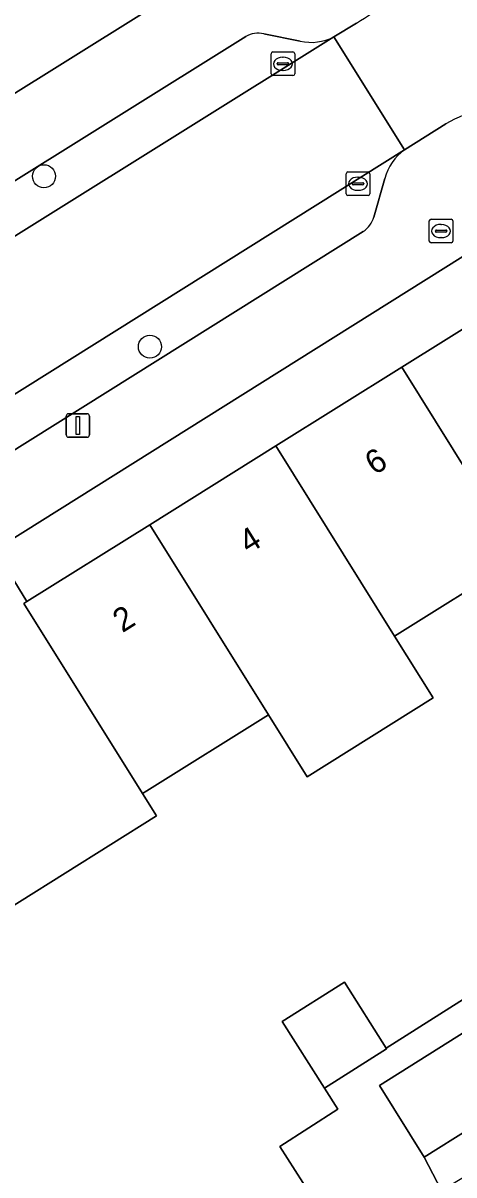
# Model space of a CAD drawing. Extents: x 159664 to 160323, y 385312 to 386115.
# Drawn here: x 160024.46 to 160042.74, y 385782.67 to 385831.48 of the extents above; entities that cross this region are included whole.
import ezdxf

# ---------------------------------------------------------------- set-up
doc = ezdxf.new("R2010")
doc.units = 0
for name, color, linetype in [('IMGEO_Boom', 7, 'Continuous'), ('IMGEO_Brandkraan', 7, 'Continuous'), ('IMGEO_Erf', 7, 'Continuous'), ('IMGEO_Kolk', 7, 'Continuous'), ('IMGEO_Lichtmast', 7, 'Continuous'), ('IMGEO_Pand', 7, 'Continuous'), ('IMGEO_Pand_nummerreeks', 7, 'Continuous'), ('IMGEO_Parkeervlak_open', 7, 'Continuous'), ('IMGEO_Rijbaan_lokaal_open', 7, 'Continuous'), ('IMGEO_Voetpad_open', 7, 'Continuous')]:
    doc.layers.add(name, color=color, linetype=linetype)

msp = doc.modelspace()

# ---------------------------------------------------------------- linework, layer by layer
at = {"layer": 'IMGEO_Boom'}
for centre in [(160025.351, 385824.986), (160029.844, 385817.765)]:
    msp.add_circle(centre, 0.489, dxfattribs=at)
at = {"layer": 'IMGEO_Brandkraan'}
for p, q in [((160041.691, 385822.238), (160041.691, 385823.09)), ((160041.766, 385823.164), (160042.618, 385823.164)), ((160042.179, 385822.944), (160042.204, 385822.944)), ((160042.692, 385823.09), (160042.692, 385822.238)), ((160041.95, 385822.658), (160041.95, 385822.67)), ((160042.388, 385822.621), (160041.99, 385822.621)), ((160041.993, 385822.707), (160042.391, 385822.707)), ((160042.434, 385822.67), (160042.434, 385822.658)), ((160042.618, 385822.164), (160041.766, 385822.164)), ((160042.202, 385822.384), (160042.177, 385822.384))]:
    msp.add_line(p, q, dxfattribs=at)
for points in [[(160041.691, 385822.238), (160041.691, 385823.09)], [(160041.766, 385823.164), (160042.618, 385823.164)], [(160042.692, 385823.09), (160042.692, 385822.238)], [(160042.618, 385822.164), (160041.766, 385822.164)]]:
    msp.add_lwpolyline(points, dxfattribs=at)
for centre, radius, start, end in [((160041.768, 385823.088), 0.0765, 91.552, 178.448), ((160041.768, 385823.088), 0.0765, 91.552, 178.448), ((160042.616, 385823.088), 0.0765, 1.552, 88.448), ((160042.616, 385823.088), 0.0765, 1.552, 88.448), ((160041.99, 385822.667), 0.0403, 85.8775, 175.7526), ((160041.987, 385822.657), 0.0366, 178.938, 274.7102), ((160042.391, 385822.664), 0.043, 264.8664, 352.4533), ((160042.395, 385822.669), 0.0386, 1.7309, 96.639), ((160041.768, 385822.24), 0.0765, 181.552, 268.448), ((160041.768, 385822.24), 0.0765, 181.552, 268.448), ((160042.616, 385822.24), 0.0765, 271.552, 358.448), ((160042.616, 385822.24), 0.0765, 271.552, 358.448)]:
    msp.add_arc(centre, radius, start, end, dxfattribs=at)
for centre, major_axis, ratio, start_param, end_param in [((160042.178, 385822.664), (-0.387, 0.002), 0.722429, 4.712389, 7.853982), ((160042.203, 385822.664), (-0.39, 0.002), 0.717154, 1.570796, 4.712389)]:
    msp.add_ellipse(centre, major_axis=major_axis, ratio=ratio, start_param=start_param, end_param=end_param, dxfattribs=at)
at = {"layer": 'IMGEO_Erf'}
for points in [[(159990.336, 385807.428), (160038.523, 385837.501)], [(160047.785, 385824.505), (159998.838, 385793.855)], [(160023.715, 385808.455), (160024.631, 385806.964), (160029.846, 385810.221), (160035.19, 385813.558), (160040.533, 385816.895), (160046.049, 385820.34)], [(160045.382, 385808.721), (160040.222, 385805.5), (160041.856, 385802.883), (160036.512, 385799.546), (160034.877, 385802.164), (160029.715, 385798.943), (160029.532, 385798.829), (160030.123, 385797.883), (160016.558, 385789.392), (160023.715, 385777.928)], [(160094.38, 385750), (160062.581, 385800.858), (160046.077, 385790.539), (160045.381, 385790.102), (160047.281, 385787.076), (160041.478, 385783.432), (160042.208, 385782.014), (160044.187, 385783.22), (160046.139, 385780.014)], [(160037.309, 385780.83), (160035.35, 385783.875), (160037.813, 385785.459), (160037.249, 385786.35), (160035.458, 385789.181), (160038.092, 385790.847), (160039.859, 385788.051), (160052.095, 385795.785)]]:
    msp.add_lwpolyline(points, dxfattribs=at)
at = {"layer": 'IMGEO_Kolk'}
for p, q in [((160035.058, 385830.252), (160035.91, 385830.252)), ((160034.983, 385829.326), (160034.983, 385830.178)), ((160035.242, 385829.746), (160035.242, 385829.758)), ((160035.68, 385829.709), (160035.282, 385829.709)), ((160035.285, 385829.795), (160035.683, 385829.795)), ((160035.471, 385830.032), (160035.496, 385830.032)), ((160035.726, 385829.758), (160035.726, 385829.746)), ((160035.984, 385830.178), (160035.984, 385829.326)), ((160035.91, 385829.252), (160035.058, 385829.252)), ((160035.494, 385829.472), (160035.469, 385829.472)), ((160038.169, 385824.243), (160038.169, 385825.095)), ((160038.244, 385825.169), (160039.096, 385825.169)), ((160038.657, 385824.949), (160038.682, 385824.949)), ((160039.17, 385825.095), (160039.17, 385824.243)), ((160038.428, 385824.663), (160038.428, 385824.675)), ((160038.866, 385824.626), (160038.468, 385824.626)), ((160038.471, 385824.712), (160038.869, 385824.712)), ((160038.68, 385824.389), (160038.655, 385824.389)), ((160038.912, 385824.675), (160038.912, 385824.663)), ((160039.096, 385824.169), (160038.244, 385824.169))]:
    msp.add_line(p, q, dxfattribs=at)
for points in [[(160035.058, 385830.252), (160035.91, 385830.252)], [(160034.983, 385829.326), (160034.983, 385830.178)], [(160035.984, 385830.178), (160035.984, 385829.326)], [(160035.91, 385829.252), (160035.058, 385829.252)], [(160038.169, 385824.243), (160038.169, 385825.095)], [(160038.244, 385825.169), (160039.096, 385825.169)], [(160039.17, 385825.095), (160039.17, 385824.243)], [(160039.096, 385824.169), (160038.244, 385824.169)]]:
    msp.add_lwpolyline(points, dxfattribs=at)
for centre, radius, start, end in [((160035.06, 385830.176), 0.0765, 91.552, 178.448), ((160035.06, 385830.176), 0.0765, 91.552, 178.448), ((160035.908, 385830.176), 0.0765, 1.552, 88.448), ((160035.908, 385830.176), 0.0765, 1.552, 88.448), ((160035.282, 385829.755), 0.0403, 85.8775, 175.7526), ((160035.279, 385829.745), 0.0366, 178.938, 274.7102), ((160035.683, 385829.752), 0.043, 264.8664, 352.4533), ((160035.687, 385829.757), 0.0386, 1.7309, 96.639), ((160035.06, 385829.328), 0.0765, 181.552, 268.448), ((160035.06, 385829.328), 0.0765, 181.552, 268.448), ((160035.908, 385829.328), 0.0765, 271.552, 358.448), ((160035.908, 385829.328), 0.0765, 271.552, 358.448), ((160038.246, 385825.093), 0.0765, 91.552, 178.448), ((160038.246, 385825.093), 0.0765, 91.552, 178.448), ((160039.094, 385825.093), 0.0765, 1.552, 88.448), ((160039.094, 385825.093), 0.0765, 1.552, 88.448), ((160038.468, 385824.672), 0.0403, 85.8775, 175.7526), ((160038.465, 385824.662), 0.0366, 178.938, 274.7102), ((160038.869, 385824.669), 0.043, 264.8664, 352.4533), ((160038.873, 385824.674), 0.0386, 1.7309, 96.639), ((160038.246, 385824.245), 0.0765, 181.552, 268.448), ((160038.246, 385824.245), 0.0765, 181.552, 268.448), ((160039.094, 385824.245), 0.0765, 271.552, 358.448), ((160039.094, 385824.245), 0.0765, 271.552, 358.448)]:
    msp.add_arc(centre, radius, start, end, dxfattribs=at)
for centre, major_axis, ratio, start_param, end_param in [((160035.47, 385829.752), (-0.387, 0.002), 0.722429, 4.712389, 7.853982), ((160035.495, 385829.752), (-0.39, 0.002), 0.717154, 1.570796, 4.712389), ((160038.656, 385824.669), (-0.387, 0.002), 0.722429, 4.712389, 7.853982), ((160038.681, 385824.669), (-0.39, 0.002), 0.717154, 1.570796, 4.712389)]:
    msp.add_ellipse(centre, major_axis=major_axis, ratio=ratio, start_param=start_param, end_param=end_param, dxfattribs=at)
at = {"layer": 'IMGEO_Lichtmast'}
for p, q in [((160026.292, 385814.025), (160026.292, 385814.825)), ((160026.292, 385814.825), (160026.292, 385814.025)), ((160026.392, 385814.925), (160027.182, 385814.925)), ((160027.182, 385814.925), (160026.392, 385814.925)), ((160027.282, 385814.825), (160027.282, 385814.025)), ((160027.282, 385814.025), (160027.282, 385814.825)), ((160027.182, 385813.925), (160026.392, 385813.925)), ((160026.392, 385813.925), (160027.182, 385813.925))]:
    msp.add_line(p, q, dxfattribs=at)
msp.add_lwpolyline([(160026.712, 385814.8), (160026.862, 385814.8), (160026.862, 385814.05), (160026.712, 385814.05), (160026.712, 385814.8)], dxfattribs=at)
for centre, start, end in [((160026.392, 385814.825), 90, 180), ((160026.392, 385814.825), 90, 180), ((160027.182, 385814.825), 0, 90), ((160027.182, 385814.825), 360, 90), ((160026.392, 385814.025), 180, 270), ((160026.392, 385814.025), 180, 270), ((160027.182, 385814.025), 270, 0), ((160027.182, 385814.025), 270, 0)]:
    msp.add_arc(centre, 0.1, start, end, dxfattribs=at)
at = {"layer": 'IMGEO_Pand'}
for points in [[(160046.049, 385820.34), (160040.533, 385816.895), (160045.566, 385808.836), (160046.625, 385807.14), (160052.147, 385810.579)], [(160040.533, 385816.895), (160035.19, 385813.558), (160040.222, 385805.5), (160045.382, 385808.721), (160045.566, 385808.836)], [(160035.19, 385813.558), (160029.846, 385810.221), (160034.877, 385802.164), (160036.512, 385799.546), (160041.856, 385802.883), (160040.222, 385805.5)], [(160029.846, 385810.221), (160024.631, 385806.964), (160024.502, 385806.884), (160029.532, 385798.829), (160029.715, 385798.943), (160034.877, 385802.164)], [(160038.092, 385790.847), (160035.458, 385789.181), (160037.249, 385786.35), (160039.882, 385788.015), (160039.859, 385788.051)], [(160045.381, 385790.102), (160039.578, 385786.458), (160041.478, 385783.432), (160047.281, 385787.076)]]:
    msp.add_lwpolyline(points, close=True, dxfattribs=at)
msp.add_lwpolyline([(160016.558, 385789.392), (160030.123, 385797.883), (160029.532, 385798.829), (160024.502, 385806.884), (160024.631, 385806.964), (160023.715, 385808.455)], dxfattribs=at)
at = {"layer": 'IMGEO_Parkeervlak_open'}
for points in [[(159993.137, 385803.124), (160037.646, 385830.886)], [(160033.911, 385830.905), (159994.835, 385806.533)], [(160036.219, 385830.71), (160034.673, 385831.023)], [(160040.643, 385826.109), (159996.221, 385798.296)], [(160039.337, 385823.258), (160039.803, 385824.888)], [(159999.803, 385798.19), (160038.885, 385822.649)]]:
    msp.add_lwpolyline(points, dxfattribs=at)
for centre, radius, start, end in [((160034.443, 385829.992), 1.057, 77.4065, 120.1988), ((160036.687, 385832.788), 2.13, 257.3091, 296.7531), ((160041.943, 385824.315), 2.216, 125.9334, 165.0137), ((160038.328, 385823.535), 1.047, 302.1781, 344.6563)]:
    msp.add_arc(centre, radius, start, end, dxfattribs=at)
at = {"layer": 'IMGEO_Rijbaan_lokaal_open'}
for points in [[(160038.603, 385831.477), (160037.646, 385830.886), (160040.643, 385826.109), (160042.395, 385827.204)], [(160040.643, 385826.109), (160037.646, 385830.886), (159993.137, 385803.124)], [(159996.221, 385798.296), (160040.643, 385826.109)]]:
    msp.add_lwpolyline(points, dxfattribs=at)
for centre, radius, start, end in [((160035.342, 385837.221), 6.605, 299.5876, 327.5425), ((160045.399, 385822.047), 5.968, 88.1648, 120.2197)]:
    msp.add_arc(centre, radius, start, end, dxfattribs=at)
at = {"layer": 'IMGEO_Voetpad_open'}
for points in [[(160040.915, 385833.676), (160038.523, 385837.501), (159990.336, 385807.428), (159993.137, 385803.124)], [(160037.646, 385830.886), (160038.603, 385831.477)], [(159994.835, 385806.533), (160033.911, 385830.905)], [(160034.673, 385831.023), (160036.219, 385830.71)], [(160042.395, 385827.204), (160040.643, 385826.109)], [(160039.803, 385824.888), (160039.337, 385823.258)], [(159996.221, 385798.296), (159998.838, 385793.855), (160047.785, 385824.505)], [(160038.885, 385822.649), (159999.803, 385798.19)], [(160042.208, 385782.014), (160041.478, 385783.432), (160039.578, 385786.458), (160045.381, 385790.102), (160046.077, 385790.539), (160062.581, 385800.858), (160061.979, 385801.821), (160058.841, 385799.87), (160056.19, 385798.208), (160054.603, 385797.213), (160054.265, 385797.001), (160052.728, 385797.851), (160052.095, 385797.416), (160052.095, 385795.785), (160039.859, 385788.051), (160039.882, 385788.015), (160037.249, 385786.35), (160037.813, 385785.459), (160035.35, 385783.875), (160037.309, 385780.83)]]:
    msp.add_lwpolyline(points, dxfattribs=at)
for centre, radius, start, end in [((160035.342, 385837.221), 6.605, 299.5876, 327.5425), ((160034.443, 385829.992), 1.057, 77.4065, 120.1988), ((160036.687, 385832.788), 2.13, 257.3091, 296.7531), ((160045.399, 385822.047), 5.968, 88.1648, 120.2197), ((160041.943, 385824.315), 2.216, 125.9334, 165.0137), ((160038.328, 385823.535), 1.047, 302.1781, 344.6563)]:
    msp.add_arc(centre, radius, start, end, dxfattribs=at)

# ---------------------------------------------------------------- texts
at = {"layer": 'IMGEO_Pand_nummerreeks'}
for s, p in [('6', (160039.368, 385812.3)), ('4', (160034.025, 385808.963)), ('2', (160028.676, 385805.622))]:
    msp.add_text(s, height=1, rotation=31.9825, dxfattribs=at).set_placement(p)

doc.saveas('drawing.dxf')
